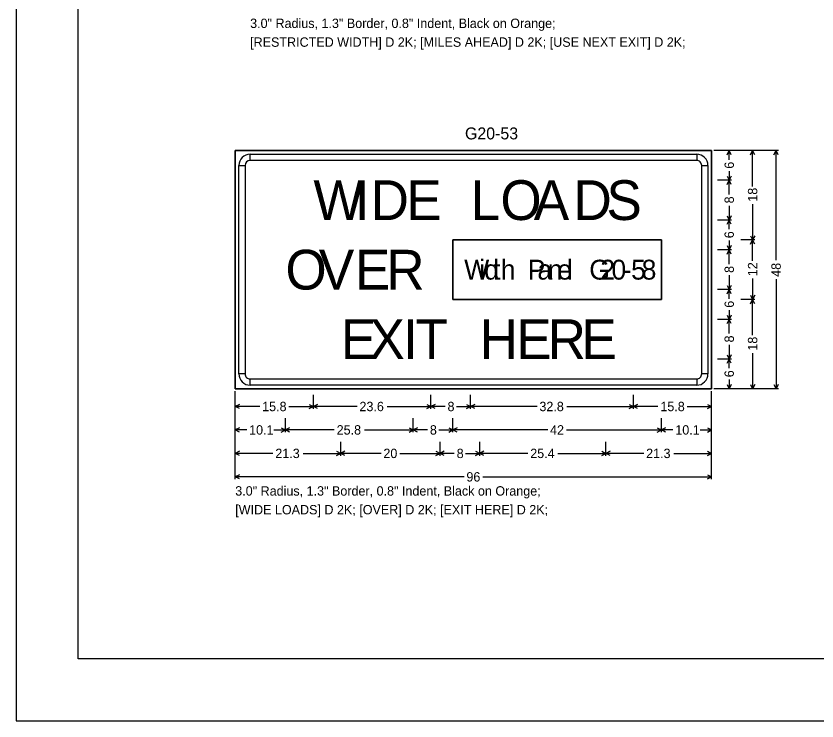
# Model space of a CAD drawing. Extents: x -1403959 to 81668, y -1400582 to 11018.
# Drawn here: x -1403959 to -1402613, y -1400582 to -1399399 of the extents above; entities that cross this region are included whole.
import ezdxf

# ---------------------------------------------------------------- set-up
doc = ezdxf.new("R2010")
doc.units = 0
for name, color, linetype in [('tdCiInt', 7, 'Continuous'), ('tdCiIntRampCL', 7, 'Continuous'), ('tdCiPriRamp', 7, 'Continuous'), ('tdRailNorfolk_South', 7, 'Continuous'), ('trf_Sign_Details_Border', 7, 'Continuous'), ('trf_Sign_Details_Dimensions', 7, 'Continuous')]:
    doc.layers.add(name, color=color, linetype=linetype)

msp = doc.modelspace()

# ---------------------------------------------------------------- linework, layer by layer
at = {"layer": 'tdCiInt'}
for p, q in [((-1403565.4, -1399641.1), (-1403565.4, -1399630.7)), ((-1402815.4, -1399630.7), (-1402815.4, -1399641.1)), ((-1403584.2, -1399649.5), (-1403573.8, -1399649.5)), ((-1402807.1, -1399649.5), (-1402796.7, -1399649.5)), ((-1402874.8, -1399774.5), (-1403224.8, -1399774.5)), ((-1403224.8, -1399774.5), (-1403224.8, -1399874.5)), ((-1402874.8, -1399874.5), (-1402874.8, -1399774.5)), ((-1403224.8, -1399874.5), (-1402874.8, -1399874.5)), ((-1403573.8, -1399999.5), (-1403584.2, -1399999.5)), ((-1402796.7, -1399999.5), (-1402807.1, -1399999.5)), ((-1403565.4, -1400018.2), (-1403565.4, -1400007.8)), ((-1402815.4, -1400007.8), (-1402815.4, -1400018.2))]:
    msp.add_line(p, q, dxfattribs=at)
for points in [[(-1403590.4, -1400024.5), (-1402790.4, -1400024.5), (-1402790.4, -1399624.5), (-1403590.4, -1399624.5), (-1403590.4, -1400024.5)], [(-1402815.4, -1399641.1), (-1403565.4, -1399641.1), (-1403565.4, -1399630.7), (-1402815.4, -1399630.7), (-1402815.4, -1399641.1)], [(-1403573.8, -1399649.5), (-1403573.8, -1399999.5), (-1403584.2, -1399999.5), (-1403584.2, -1399649.5), (-1403573.8, -1399649.5)], [(-1402807.1, -1399999.5), (-1402807.1, -1399649.5), (-1402796.7, -1399649.5), (-1402796.7, -1399999.5), (-1402807.1, -1399999.5)], [(-1403565.4, -1400007.8), (-1402815.4, -1400007.8), (-1402815.4, -1400018.2), (-1403565.4, -1400018.2), (-1403565.4, -1400007.8)]]:
    msp.add_lwpolyline(points, close=True, dxfattribs=at)
for centre, radius, start, end in [((-1403565.4, -1399649.5), 18.8, 90.0002, 179.9998), ((-1402815.4, -1399649.5), 18.8, 0, 90.0002), ((-1403565.4, -1399649.5), 8.33, 90.0002, 179.9998), ((-1402815.4, -1399649.5), 8.33, 0, 90.0002), ((-1403565.4, -1399999.5), 18.8, 179.9998, 270.0001), ((-1403565.4, -1399999.5), 8.33, 179.9998, 270.0001), ((-1402815.4, -1399999.5), 18.8, 270.0001, 0.0003), ((-1402815.4, -1399999.5), 8.33, 270.0001, 0.0003)]:
    msp.add_arc(centre, radius, start, end, dxfattribs=at)
at = {"layer": 'tdCiIntRampCL'}
msp.add_lwpolyline([(-1403958.5, -1400581.8), (-1400614.5, -1400581.8), (-1400614.5, -1397997.8), (-1403958.5, -1397997.8)], close=True, dxfattribs=at)
at = {"layer": 'tdCiPriRamp'}
msp.add_lwpolyline([(-1403854, -1398467.3), (-1400719, -1398467.3), (-1400719, -1400477.3), (-1403854, -1400477.3)], close=True, dxfattribs=at)
at = {"layer": 'trf_Sign_Details_Border'}
for points in [[(-1403590.4, -1399624.5), (-1402790.4, -1399624.5), (-1402790.4, -1400024.5), (-1403590.4, -1400024.5)], [(-1403224.8, -1399774.5), (-1402874.8, -1399774.5), (-1402874.8, -1399874.5), (-1403224.8, -1399874.5)]]:
    msp.add_lwpolyline(points, close=True, dxfattribs=at)
at = {"layer": 'trf_Sign_Details_Dimensions'}
for p, q in [((-1402678.2, -1399624.5), (-1402786.5, -1399624.5)), ((-1402757, -1399624.5), (-1402780.6, -1399624.5)), ((-1402764.4, -1399631.5), (-1402760.9, -1399624.5)), ((-1402760.9, -1399640), (-1402760.9, -1399624.5)), ((-1402757.4, -1399631.5), (-1402760.9, -1399624.5)), ((-1402717.6, -1399624.5), (-1402741.2, -1399624.5)), ((-1402725.1, -1399631.5), (-1402721.5, -1399624.5)), ((-1402721.5, -1399684.6), (-1402721.5, -1399624.5)), ((-1402718, -1399631.5), (-1402721.5, -1399624.5)), ((-1402685.7, -1399631.5), (-1402682.2, -1399624.5)), ((-1402682.2, -1399808.5), (-1402682.2, -1399624.5)), ((-1402678.6, -1399631.5), (-1402682.2, -1399624.5)), ((-1402760.9, -1399658.9), (-1402760.9, -1399674.5)), ((-1402757, -1399674.5), (-1402780.6, -1399674.5)), ((-1402764.4, -1399667.4), (-1402760.9, -1399674.5)), ((-1402764.4, -1399681.5), (-1402760.9, -1399674.5)), ((-1402757.4, -1399667.4), (-1402760.9, -1399674.5)), ((-1402760.9, -1399698.4), (-1402760.9, -1399674.5)), ((-1402757.4, -1399681.5), (-1402760.9, -1399674.5)), ((-1402760.9, -1399717.2), (-1402760.9, -1399741.1)), ((-1402721.5, -1399714.4), (-1402721.5, -1399774.5)), ((-1402757, -1399741.1), (-1402780.6, -1399741.1)), ((-1402764.4, -1399734.1), (-1402760.9, -1399741.1)), ((-1402764.4, -1399748.2), (-1402760.9, -1399741.1)), ((-1402757.4, -1399734.1), (-1402760.9, -1399741.1)), ((-1402760.9, -1399756.7), (-1402760.9, -1399741.1)), ((-1402757.4, -1399748.2), (-1402760.9, -1399741.1)), ((-1402725.1, -1399767.4), (-1402721.5, -1399774.5)), ((-1402718, -1399767.4), (-1402721.5, -1399774.5)), ((-1402764.4, -1399784.1), (-1402760.9, -1399791.1)), ((-1402760.9, -1399775.6), (-1402760.9, -1399791.1)), ((-1402757.4, -1399784.1), (-1402760.9, -1399791.1)), ((-1402717.6, -1399774.5), (-1402741.2, -1399774.5)), ((-1402725.1, -1399781.5), (-1402721.5, -1399774.5)), ((-1402721.5, -1399809.7), (-1402721.5, -1399774.5)), ((-1402718, -1399781.5), (-1402721.5, -1399774.5)), ((-1402757, -1399791.1), (-1402780.6, -1399791.1)), ((-1402764.4, -1399798.2), (-1402760.9, -1399791.1)), ((-1402760.9, -1399815.1), (-1402760.9, -1399791.1)), ((-1402757.4, -1399798.2), (-1402760.9, -1399791.1)), ((-1402760.9, -1399833.8), (-1402760.9, -1399857.8)), ((-1402764.4, -1399850.8), (-1402760.9, -1399857.8)), ((-1402757.4, -1399850.8), (-1402760.9, -1399857.8)), ((-1402721.5, -1399839.3), (-1402721.5, -1399874.5)), ((-1402682.2, -1399840.4), (-1402682.2, -1400024.5)), ((-1402757, -1399857.8), (-1402780.6, -1399857.8)), ((-1402764.4, -1399864.8), (-1402760.9, -1399857.8)), ((-1402760.9, -1399873.3), (-1402760.9, -1399857.8)), ((-1402757.4, -1399864.8), (-1402760.9, -1399857.8)), ((-1402717.6, -1399874.5), (-1402741.2, -1399874.5)), ((-1402717.6, -1399874.5), (-1402741.2, -1399874.5)), ((-1402725.1, -1399867.4), (-1402721.5, -1399874.5)), ((-1402725.1, -1399881.5), (-1402721.5, -1399874.5)), ((-1402718, -1399867.4), (-1402721.5, -1399874.5)), ((-1402721.5, -1399934.6), (-1402721.5, -1399874.5)), ((-1402718, -1399881.5), (-1402721.5, -1399874.5)), ((-1402764.4, -1399900.8), (-1402760.9, -1399907.8)), ((-1402760.9, -1399892.3), (-1402760.9, -1399907.8)), ((-1402757.4, -1399900.8), (-1402760.9, -1399907.8)), ((-1402757, -1399907.8), (-1402780.6, -1399907.8)), ((-1402764.4, -1399914.8), (-1402760.9, -1399907.8)), ((-1402760.9, -1399931.8), (-1402760.9, -1399907.8)), ((-1402757.4, -1399914.8), (-1402760.9, -1399907.8)), ((-1402760.9, -1399950.5), (-1402760.9, -1399974.5)), ((-1402764.4, -1399967.4), (-1402760.9, -1399974.5)), ((-1402757.4, -1399967.4), (-1402760.9, -1399974.5)), ((-1402721.5, -1399964.4), (-1402721.5, -1400024.5)), ((-1402757, -1399974.5), (-1402780.6, -1399974.5)), ((-1402757, -1399974.5), (-1402780.6, -1399974.5)), ((-1402764.4, -1399981.5), (-1402760.9, -1399974.5)), ((-1402760.9, -1399990), (-1402760.9, -1399974.5)), ((-1402757.4, -1399981.5), (-1402760.9, -1399974.5)), ((-1402760.9, -1400008.9), (-1402760.9, -1400024.5)), ((-1402678.2, -1400024.5), (-1402786.5, -1400024.5)), ((-1402757, -1400024.5), (-1402780.6, -1400024.5)), ((-1402764.4, -1400017.4), (-1402760.9, -1400024.5)), ((-1402757.4, -1400017.4), (-1402760.9, -1400024.5)), ((-1402717.6, -1400024.5), (-1402741.2, -1400024.5)), ((-1402725.1, -1400017.4), (-1402721.5, -1400024.5)), ((-1402718, -1400017.4), (-1402721.5, -1400024.5)), ((-1402685.7, -1400017.4), (-1402682.2, -1400024.5)), ((-1402678.6, -1400017.4), (-1402682.2, -1400024.5)), ((-1403590.4, -1400176), (-1403590.4, -1400028.4)), ((-1403590.4, -1400057.9), (-1403590.4, -1400034.3)), ((-1403459.1, -1400057.9), (-1403459.1, -1400034.3)), ((-1403261.8, -1400057.9), (-1403261.8, -1400034.3)), ((-1403195.1, -1400057.9), (-1403195.1, -1400034.3)), ((-1402921.8, -1400057.9), (-1402921.8, -1400034.3)), ((-1402921.8, -1400057.9), (-1402921.8, -1400034.3)), ((-1402790.4, -1400176), (-1402790.4, -1400028.4)), ((-1402790.4, -1400057.9), (-1402790.4, -1400034.3)), ((-1403583.4, -1400050.5), (-1403590.4, -1400054)), ((-1403466.1, -1400050.5), (-1403459.1, -1400054)), ((-1403452.1, -1400050.5), (-1403459.1, -1400054)), ((-1403268.8, -1400050.5), (-1403261.8, -1400054)), ((-1403254.7, -1400050.5), (-1403261.8, -1400054)), ((-1403202.1, -1400050.5), (-1403195.1, -1400054)), ((-1403188.1, -1400050.5), (-1403195.1, -1400054)), ((-1402928.8, -1400050.5), (-1402921.8, -1400054)), ((-1402914.7, -1400050.5), (-1402921.8, -1400054)), ((-1402797.5, -1400050.5), (-1402790.4, -1400054)), ((-1403549.1, -1400054), (-1403590.4, -1400054)), ((-1403583.4, -1400057.5), (-1403590.4, -1400054)), ((-1403500.4, -1400054), (-1403459.1, -1400054)), ((-1403466.1, -1400057.5), (-1403459.1, -1400054)), ((-1403385.8, -1400054), (-1403459.1, -1400054)), ((-1403452.1, -1400057.5), (-1403459.1, -1400054)), ((-1403335.1, -1400054), (-1403261.8, -1400054)), ((-1403268.8, -1400057.5), (-1403261.8, -1400054)), ((-1403237.8, -1400054), (-1403261.8, -1400054)), ((-1403254.7, -1400057.5), (-1403261.8, -1400054)), ((-1403219.1, -1400054), (-1403195.1, -1400054)), ((-1403202.1, -1400057.5), (-1403195.1, -1400054)), ((-1403083.5, -1400054), (-1403195.1, -1400054)), ((-1403188.1, -1400057.5), (-1403195.1, -1400054)), ((-1403033.3, -1400054), (-1402921.8, -1400054)), ((-1402928.8, -1400057.5), (-1402921.8, -1400054)), ((-1402880.5, -1400054), (-1402921.8, -1400054)), ((-1402914.7, -1400057.5), (-1402921.8, -1400054)), ((-1402831.7, -1400054), (-1402790.4, -1400054)), ((-1402797.5, -1400057.5), (-1402790.4, -1400054)), ((-1403590.4, -1400097.3), (-1403590.4, -1400073.7)), ((-1403506.1, -1400097.3), (-1403506.1, -1400073.7)), ((-1403291.4, -1400097.3), (-1403291.4, -1400073.7)), ((-1403224.8, -1400097.3), (-1403224.8, -1400073.7)), ((-1402874.8, -1400097.3), (-1402874.8, -1400073.7)), ((-1402874.8, -1400097.3), (-1402874.8, -1400073.7)), ((-1402790.4, -1400097.3), (-1402790.4, -1400073.7)), ((-1403583.4, -1400089.8), (-1403590.4, -1400093.4)), ((-1403571, -1400093.4), (-1403590.4, -1400093.4)), ((-1403583.4, -1400096.9), (-1403590.4, -1400093.4)), ((-1403525.5, -1400093.4), (-1403506.1, -1400093.4)), ((-1403513.1, -1400089.8), (-1403506.1, -1400093.4)), ((-1403513.1, -1400096.9), (-1403506.1, -1400093.4)), ((-1403499.1, -1400089.8), (-1403506.1, -1400093.4)), ((-1403424, -1400093.4), (-1403506.1, -1400093.4)), ((-1403499.1, -1400096.9), (-1403506.1, -1400093.4)), ((-1403373.5, -1400093.4), (-1403291.4, -1400093.4)), ((-1403298.5, -1400089.8), (-1403291.4, -1400093.4)), ((-1403298.5, -1400096.9), (-1403291.4, -1400093.4)), ((-1403284.4, -1400089.8), (-1403291.4, -1400093.4)), ((-1403267.5, -1400093.4), (-1403291.4, -1400093.4)), ((-1403284.4, -1400096.9), (-1403291.4, -1400093.4)), ((-1403248.7, -1400093.4), (-1403224.8, -1400093.4)), ((-1403231.8, -1400089.8), (-1403224.8, -1400093.4)), ((-1403231.8, -1400096.9), (-1403224.8, -1400093.4)), ((-1403217.7, -1400089.8), (-1403224.8, -1400093.4)), ((-1403065.7, -1400093.4), (-1403224.8, -1400093.4)), ((-1403217.7, -1400096.9), (-1403224.8, -1400093.4)), ((-1403033.9, -1400093.4), (-1402874.8, -1400093.4)), ((-1402881.8, -1400089.8), (-1402874.8, -1400093.4)), ((-1402881.8, -1400096.9), (-1402874.8, -1400093.4)), ((-1402867.7, -1400089.8), (-1402874.8, -1400093.4)), ((-1402855.4, -1400093.4), (-1402874.8, -1400093.4)), ((-1402867.7, -1400096.9), (-1402874.8, -1400093.4)), ((-1402809.8, -1400093.4), (-1402790.4, -1400093.4)), ((-1402797.5, -1400089.8), (-1402790.4, -1400093.4)), ((-1402797.5, -1400096.9), (-1402790.4, -1400093.4)), ((-1403590.4, -1400136.7), (-1403590.4, -1400113.1)), ((-1403413.1, -1400136.7), (-1403413.1, -1400113.1)), ((-1403246.4, -1400136.7), (-1403246.4, -1400113.1)), ((-1403179.8, -1400136.7), (-1403179.8, -1400113.1)), ((-1402967.8, -1400136.7), (-1402967.8, -1400113.1)), ((-1402967.8, -1400136.7), (-1402967.8, -1400113.1)), ((-1402790.4, -1400136.7), (-1402790.4, -1400113.1)), ((-1403583.4, -1400129.2), (-1403590.4, -1400132.7)), ((-1403527, -1400132.7), (-1403590.4, -1400132.7)), ((-1403583.4, -1400136.3), (-1403590.4, -1400132.7)), ((-1403476.5, -1400132.7), (-1403413.1, -1400132.7)), ((-1403420.1, -1400129.2), (-1403413.1, -1400132.7)), ((-1403420.1, -1400136.3), (-1403413.1, -1400132.7)), ((-1403406.1, -1400129.2), (-1403413.1, -1400132.7)), ((-1403345.5, -1400132.7), (-1403413.1, -1400132.7)), ((-1403406.1, -1400136.3), (-1403413.1, -1400132.7)), ((-1403314, -1400132.7), (-1403246.4, -1400132.7)), ((-1403253.5, -1400129.2), (-1403246.4, -1400132.7)), ((-1403253.5, -1400136.3), (-1403246.4, -1400132.7)), ((-1403239.4, -1400129.2), (-1403246.4, -1400132.7)), ((-1403222.5, -1400132.7), (-1403246.4, -1400132.7)), ((-1403239.4, -1400136.3), (-1403246.4, -1400132.7)), ((-1403203.7, -1400132.7), (-1403179.8, -1400132.7)), ((-1403186.8, -1400129.2), (-1403179.8, -1400132.7)), ((-1403186.8, -1400136.3), (-1403179.8, -1400132.7)), ((-1403172.7, -1400129.2), (-1403179.8, -1400132.7)), ((-1403098.9, -1400132.7), (-1403179.8, -1400132.7)), ((-1403172.7, -1400136.3), (-1403179.8, -1400132.7)), ((-1403048.6, -1400132.7), (-1402967.8, -1400132.7)), ((-1402974.8, -1400129.2), (-1402967.8, -1400132.7)), ((-1402974.8, -1400136.3), (-1402967.8, -1400132.7)), ((-1402960.7, -1400129.2), (-1402967.8, -1400132.7)), ((-1402904.3, -1400132.7), (-1402967.8, -1400132.7)), ((-1402960.7, -1400136.3), (-1402967.8, -1400132.7)), ((-1402853.8, -1400132.7), (-1402790.4, -1400132.7)), ((-1402797.5, -1400129.2), (-1402790.4, -1400132.7)), ((-1402797.5, -1400136.3), (-1402790.4, -1400132.7)), ((-1403583.4, -1400168.6), (-1403590.4, -1400172.1)), ((-1403206.2, -1400172.1), (-1403590.4, -1400172.1)), ((-1403583.4, -1400175.6), (-1403590.4, -1400172.1)), ((-1403174.7, -1400172.1), (-1402790.4, -1400172.1)), ((-1402797.5, -1400168.6), (-1402790.4, -1400172.1)), ((-1402797.5, -1400175.6), (-1402790.4, -1400172.1))]:
    msp.add_line(p, q, dxfattribs=at)

# ---------------------------------------------------------------- texts
at = {"layer": 'tdCiInt'}
for s, height, p in [('W', 66.7, (-1403459.1, -1399741.1)), ('I', 66.7, (-1403389.8, -1399741.1)), ('D', 66.7, (-1403363.1, -1399741.1)), ('E', 66.7, (-1403303.1, -1399741.1)), ('L', 66.7, (-1403195.1, -1399741.1)), ('O', 66.7, (-1403145.1, -1399741.1)), ('A', 66.7, (-1403089.1, -1399741.1)), ('D', 66.7, (-1403022.4, -1399741.1)), ('S', 66.7, (-1402967.1, -1399741.1)), ('O', 66.7, (-1403506.1, -1399857.8)), ('V', 66.7, (-1403450.1, -1399857.8)), ('E', 66.7, (-1403389.4, -1399857.8)), ('R', 66.7, (-1403336.8, -1399857.8)), ('W', 33.3, (-1403205.9, -1399841.1)), ('i', 33.3, (-1403180.9, -1399841.1)), ('d', 33.3, (-1403172.3, -1399841.1)), ('t', 33.3, (-1403157.3, -1399841.1)), ('h', 33.3, (-1403144.6, -1399841.1)), ('P', 33.3, (-1403099.3, -1399841.1)), ('l', 33.3, (-1403033.6, -1399841.1)), ('G', 33.3, (-1402995.9, -1399841.1)), ('2', 33.3, (-1402977.3, -1399841.1)), ('0', 33.3, (-1402958.6, -1399841.1)), ('5', 33.3, (-1402925.6, -1399841.1)), ('8', 33.3, (-1402907.9, -1399841.1)), ('a', 33.3, (-1403082.9, -1399841.1)), ('n', 33.3, (-1403065.6, -1399841.1)), ('e', 33.3, (-1403049.6, -1399841.1)), ('-', 33.3, (-1402939.6, -1399841.1)), ('E', 66.7, (-1403413.1, -1399974.5)), ('X', 66.7, (-1403365.1, -1399974.5)), ('I', 66.7, (-1403308.4, -1399974.5)), ('T', 66.7, (-1403287.8, -1399974.5)), ('H', 66.7, (-1403179.8, -1399974.5)), ('E', 66.7, (-1403118.4, -1399974.5)), ('R', 66.7, (-1403065.8, -1399974.5)), ('E', 66.7, (-1403009.1, -1399974.5))]:
    msp.add_text(s, height=height, dxfattribs=at).set_placement(p)
at = {"layer": 'tdRailNorfolk_South'}
msp.add_text('G20-53', height=20, dxfattribs=at).set_placement((-1403204.6, -1399605.8))
at = {"layer": 'trf_Sign_Details_Dimensions'}
for s, height, p in [('3.0" Radius, 1.3" Border, 0.8" Indent, Black on Orange; ', 15.748, (-1403565.4, -1399418.9)), ('[RESTRICTED WIDTH] D 2K; [MILES AHEAD] D 2K; [USE NEXT EXIT] D 2K; ', 15.748, (-1403565.4, -1399450.4)), ('15.8', 15.75, (-1403545.2, -1400061.9)), ('23.6', 15.75, (-1403381.8, -1400061.9)), ('8', 15.7, (-1403233.9, -1400061.9)), ('32.8', 15.75, (-1403079.6, -1400061.9)), ('15.8', 15.75, (-1402876.5, -1400061.9)), ('10.1', 15.75, (-1403567.1, -1400101.2)), ('25.8', 15.75, (-1403420.1, -1400101.2)), ('8', 15.7, (-1403263.5, -1400101.2)), ('42', 15.75, (-1403061.7, -1400101.2)), ('10.1', 15.75, (-1402851.4, -1400101.2)), ('21.3', 15.75, (-1403523.1, -1400140.6)), ('20', 15.75, (-1403341.6, -1400140.6)), ('8', 15.7, (-1403218.5, -1400140.6)), ('25.4', 15.75, (-1403095, -1400140.6)), ('21.3', 15.75, (-1402900.4, -1400140.6)), ('96', 15.75, (-1403202.2, -1400180)), ('3.0" Radius, 1.3" Border, 0.8" Indent, Black on Orange; ', 15.748, (-1403590.4, -1400203.6)), ('[WIDE LOADS] D 2K; [OVER] D 2K; [EXIT HERE] D 2K; ', 15.748, (-1403590.4, -1400235.1))]:
    msp.add_text(s, height=height, dxfattribs=at).set_placement(p)
for s, height, p in [('6', 15.7, (-1402753, -1399655)), ('18', 15.75, (-1402713.7, -1399710.4)), ('8', 15.7, (-1402753, -1399713.2)), ('6', 15.7, (-1402753, -1399771.7)), ('8', 15.7, (-1402753, -1399829.9)), ('12', 15.75, (-1402713.7, -1399835.4)), ('48', 15.75, (-1402674.3, -1399836.5)), ('6', 15.7, (-1402753, -1399888.3)), ('8', 15.7, (-1402753, -1399946.6)), ('18', 15.75, (-1402713.7, -1399960.4)), ('6', 15.7, (-1402753, -1400005))]:
    msp.add_text(s, height=height, rotation=90.0002, dxfattribs=at).set_placement(p)

doc.saveas('drawing.dxf')
